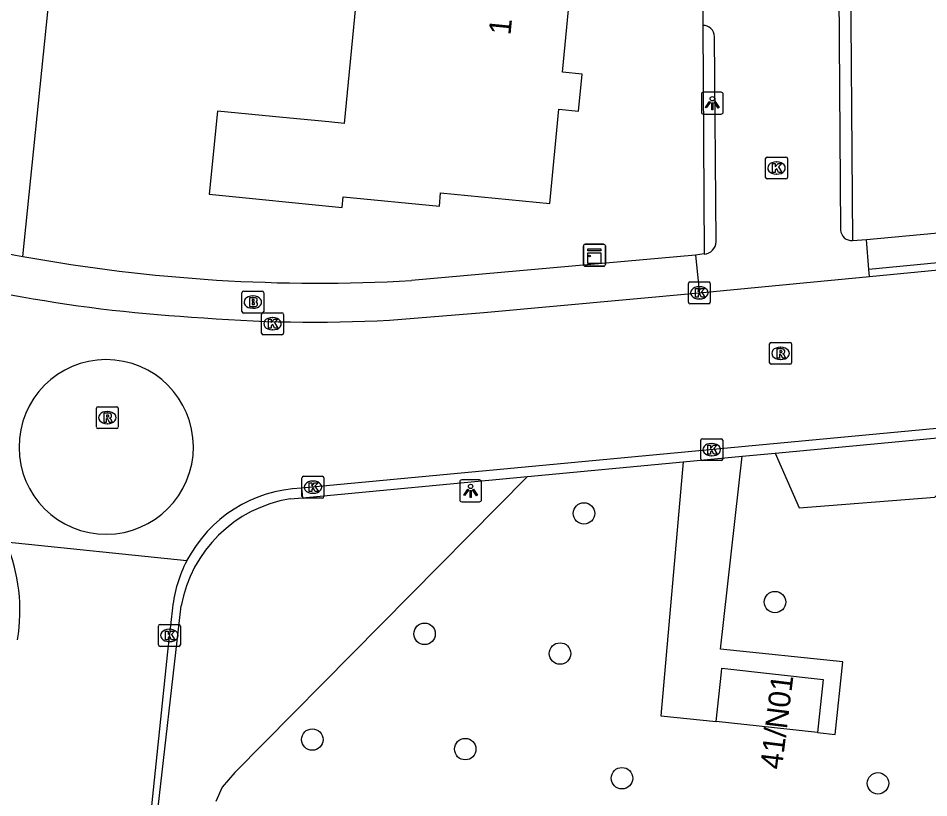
# Model space of a CAD drawing. Extents: x 162157 to 163165, y 378998 to 380775.
# Drawn here: x 162295.27 to 162336.77, y 380611.42 to 380646.95 of the extents above; entities that cross this region are included whole.
import ezdxf

# ---------------------------------------------------------------- set-up
doc = ezdxf.new("R2010")
doc.units = 0
for name, color, linetype in [('IMGEO_Boom', 7, 'Continuous'), ('IMGEO_Brandkraan', 7, 'Continuous'), ('IMGEO_Groenvoorziening', 7, 'Continuous'), ('IMGEO_Kast', 7, 'Continuous'), ('IMGEO_Kolk', 7, 'Continuous'), ('IMGEO_Lichtpunt', 7, 'Continuous'), ('IMGEO_Pand', 7, 'Continuous'), ('IMGEO_Pand_nummerreeks', 7, 'Continuous'), ('IMGEO_Rijbaan_lokaal_gesloten', 7, 'Continuous'), ('IMGEO_Rijbaan_lokaal_open', 7, 'Continuous'), ('IMGEO_Rioolput', 7, 'Continuous'), ('IMGEO_Voetpad_open', 7, 'Continuous')]:
    doc.layers.add(name, color=color, linetype=linetype)

msp = doc.modelspace()

# ---------------------------------------------------------------- linework, layer by layer
at = {"layer": 'IMGEO_Boom'}
for centre in [(162321.052, 380624.382), (162329.757, 380620.341), (162313.788, 380618.894), (162319.962, 380617.996), (162308.671, 380614.076), (162315.641, 380613.64), (162322.783, 380612.315), (162334.452, 380612.082)]:
    msp.add_circle(centre, 0.489, dxfattribs=at)
at = {"layer": 'IMGEO_Brandkraan'}
for p, q in [((162305.46, 380633.589), (162305.46, 380634.441)), ((162305.535, 380634.515), (162306.387, 380634.515)), ((162305.948, 380634.295), (162305.973, 380634.295)), ((162306.461, 380634.441), (162306.461, 380633.589)), ((162306.387, 380633.515), (162305.535, 380633.515)), ((162305.971, 380633.735), (162305.946, 380633.735))]:
    msp.add_line(p, q, dxfattribs=at)
for points in [[(162305.46, 380633.589), (162305.46, 380634.441)], [(162305.535, 380634.515), (162306.387, 380634.515)], [(162305.808, 380634.215), (162305.808, 380633.815), (162306.021, 380633.815)], [(162306.039, 380634.215), (162305.808, 380634.215)], [(162306.461, 380634.441), (162306.461, 380633.589)], [(162305.987, 380634.134), (162305.933, 380634.134), (162305.933, 380634.058)], [(162305.933, 380634.058), (162305.986, 380634.058)], [(162305.995, 380633.982), (162305.933, 380633.982), (162305.933, 380633.901)], [(162305.933, 380633.901), (162305.995, 380633.901)], [(162306.387, 380633.515), (162305.535, 380633.515)]]:
    msp.add_lwpolyline(points, dxfattribs=at)
for centre, radius, start, end in [((162305.537, 380634.439), 0.0765, 91.552, 178.448), ((162305.537, 380634.439), 0.0765, 91.552, 178.448), ((162306.043, 380634.07), 0.145, 59.4692, 91.5367), ((162306.385, 380634.439), 0.0765, 1.552, 88.448), ((162306.385, 380634.439), 0.0765, 1.552, 88.448), ((162305.988, 380634.096), 0.0379, 267.8285, 90.9355), ((162305.996, 380633.941), 0.0404, 269.8759, 90.5077), ((162306.027, 380634.066), 0.251, 268.6676, 293.5347), ((162306.068, 380634.117), 0.0922, 285.5137, 58.1501), ((162306.073, 380633.925), 0.105, 301.3115, 78.989), ((162305.537, 380633.591), 0.0765, 181.552, 268.448), ((162305.537, 380633.591), 0.0765, 181.552, 268.448), ((162306.385, 380633.591), 0.0765, 271.552, 358.448), ((162306.385, 380633.591), 0.0765, 271.552, 358.448)]:
    msp.add_arc(centre, radius, start, end, dxfattribs=at)
for centre, major_axis, ratio, start_param, end_param in [((162305.947, 380634.015), (-0.387, 0.002), 0.722429, 4.712389, 7.853982), ((162305.972, 380634.015), (-0.39, 0.002), 0.717154, 1.570796, 4.712389)]:
    msp.add_ellipse(centre, major_axis=major_axis, ratio=ratio, start_param=start_param, end_param=end_param, dxfattribs=at)
at = {"layer": 'IMGEO_Groenvoorziening'}
for points in [[(162295.473, 380636.096), (162301.962, 380699.607), (162302.171, 380699.713), (162304.371, 380721.939), (162315.245, 380730.525)], [(162329.764, 380627.128), (162330.857, 380624.636), (162337.051, 380625.119), (162337.938, 380625.997), (162339.039, 380626.343)], [(162318.483, 380626.064), (162305.138, 380612.567), (162304.556, 380611.905), (162304.277, 380611.251)]]:
    msp.add_lwpolyline(points, dxfattribs=at)
at = {"layer": 'IMGEO_Kast'}
for p, q in [((162321.028, 380635.725), (162321.028, 380636.566)), ((162321.028, 380636.566), (162321.028, 380635.725)), ((162321.103, 380636.65), (162321.944, 380636.65)), ((162321.944, 380636.65), (162321.103, 380636.65)), ((162322.028, 380636.575), (162322.028, 380635.734)), ((162322.028, 380635.734), (162322.028, 380636.575)), ((162321.953, 380635.65), (162321.112, 380635.65)), ((162321.112, 380635.65), (162321.953, 380635.65))]:
    msp.add_line(p, q, dxfattribs=at)
for points in [[(162321.223, 380636.44), (162321.823, 380636.44), (162321.823, 380636.355), (162321.223, 380636.355), (162321.223, 380636.44)], [(162321.223, 380636.265), (162321.823, 380636.265), (162321.823, 380635.776), (162321.223, 380635.776), (162321.223, 380636.265)]]:
    msp.add_lwpolyline(points, dxfattribs=at)
msp.add_circle((162321.307, 380636.114), 0.0377, dxfattribs=at)
for centre, start, end in [((162321.106, 380636.572), 92.4484, 184.2845), ((162321.106, 380636.572), 92.4484, 184.2845), ((162321.95, 380636.572), 2.4484, 94.2845), ((162321.95, 380636.572), 2.4484, 94.2845), ((162321.106, 380635.728), 182.4484, 274.2845), ((162321.106, 380635.728), 182.4484, 274.2845), ((162321.95, 380635.728), 272.4484, 4.2845), ((162321.95, 380635.728), 272.4484, 4.2845)]:
    msp.add_arc(centre, 0.0779, start, end, dxfattribs=at)
at = {"layer": 'IMGEO_Kolk'}
for p, q in [((162329.327, 380639.699), (162329.327, 380640.551)), ((162329.402, 380640.625), (162330.254, 380640.625)), ((162330.328, 380640.551), (162330.328, 380639.699)), ((162329.815, 380640.405), (162329.84, 380640.405)), ((162330.254, 380639.625), (162329.402, 380639.625)), ((162329.838, 380639.845), (162329.813, 380639.845)), ((162325.81, 380634.01), (162325.81, 380634.862)), ((162325.885, 380634.936), (162326.737, 380634.936)), ((162326.298, 380634.716), (162326.323, 380634.716)), ((162326.811, 380634.862), (162326.811, 380634.01)), ((162326.737, 380633.936), (162325.885, 380633.936)), ((162326.321, 380634.156), (162326.296, 380634.156)), ((162306.357, 380632.603), (162306.357, 380633.455)), ((162306.432, 380633.529), (162307.284, 380633.529)), ((162307.358, 380633.455), (162307.358, 380632.603)), ((162306.845, 380633.309), (162306.87, 380633.309)), ((162306.868, 380632.749), (162306.843, 380632.749)), ((162307.284, 380632.529), (162306.432, 380632.529)), ((162326.377, 380626.862), (162326.377, 380627.714)), ((162326.452, 380627.788), (162327.304, 380627.788)), ((162326.865, 380627.568), (162326.89, 380627.568)), ((162327.378, 380627.714), (162327.378, 380626.862)), ((162327.304, 380626.788), (162326.452, 380626.788)), ((162326.888, 380627.008), (162326.863, 380627.008)), ((162308.201, 380625.152), (162308.201, 380626.004)), ((162308.276, 380626.078), (162309.128, 380626.078)), ((162309.202, 380626.004), (162309.202, 380625.152)), ((162308.689, 380625.858), (162308.714, 380625.858)), ((162309.128, 380625.078), (162308.276, 380625.078)), ((162308.712, 380625.298), (162308.687, 380625.298)), ((162301.732, 380619.322), (162302.584, 380619.322)), ((162301.657, 380618.396), (162301.657, 380619.248)), ((162302.145, 380619.102), (162302.17, 380619.102)), ((162302.658, 380619.248), (162302.658, 380618.396)), ((162302.168, 380618.542), (162302.143, 380618.542)), ((162302.584, 380618.322), (162301.732, 380618.322))]:
    msp.add_line(p, q, dxfattribs=at)
for points in [[(162329.327, 380639.699), (162329.327, 380640.551)], [(162329.402, 380640.625), (162330.254, 380640.625)], [(162330.328, 380640.551), (162330.328, 380639.699)], [(162329.648, 380640.325), (162329.771, 380640.325), (162329.771, 380640.174), (162329.901, 380640.325), (162330.065, 380640.325), (162329.919, 380640.174), (162330.072, 380639.925), (162329.92, 380639.925), (162329.835, 380640.089), (162329.771, 380640.022), (162329.771, 380639.925), (162329.648, 380639.925), (162329.648, 380640.325)], [(162330.254, 380639.625), (162329.402, 380639.625)], [(162325.81, 380634.01), (162325.81, 380634.862)], [(162325.885, 380634.936), (162326.737, 380634.936)], [(162326.131, 380634.636), (162326.254, 380634.636), (162326.254, 380634.485), (162326.384, 380634.636), (162326.548, 380634.636), (162326.402, 380634.485), (162326.555, 380634.236), (162326.403, 380634.236), (162326.318, 380634.4), (162326.254, 380634.333), (162326.254, 380634.236), (162326.131, 380634.236), (162326.131, 380634.636)], [(162326.811, 380634.862), (162326.811, 380634.01)], [(162326.737, 380633.936), (162325.885, 380633.936)], [(162306.357, 380632.603), (162306.357, 380633.455)], [(162306.432, 380633.529), (162307.284, 380633.529)], [(162307.358, 380633.455), (162307.358, 380632.603)], [(162306.678, 380633.229), (162306.801, 380633.229), (162306.801, 380633.078), (162306.931, 380633.229), (162307.095, 380633.229), (162306.949, 380633.078), (162307.102, 380632.829), (162306.95, 380632.829), (162306.865, 380632.993), (162306.801, 380632.926), (162306.801, 380632.829), (162306.678, 380632.829), (162306.678, 380633.229)], [(162307.284, 380632.529), (162306.432, 380632.529)], [(162326.377, 380626.862), (162326.377, 380627.714)], [(162326.452, 380627.788), (162327.304, 380627.788)], [(162327.378, 380627.714), (162327.378, 380626.862)], [(162326.698, 380627.488), (162326.821, 380627.488), (162326.821, 380627.337), (162326.951, 380627.488), (162327.115, 380627.488), (162326.969, 380627.337), (162327.122, 380627.088), (162326.97, 380627.088), (162326.885, 380627.252), (162326.821, 380627.185), (162326.821, 380627.088), (162326.698, 380627.088), (162326.698, 380627.488)], [(162327.304, 380626.788), (162326.452, 380626.788)], [(162308.201, 380625.152), (162308.201, 380626.004)], [(162308.276, 380626.078), (162309.128, 380626.078)], [(162309.202, 380626.004), (162309.202, 380625.152)], [(162308.522, 380625.778), (162308.645, 380625.778), (162308.645, 380625.627), (162308.775, 380625.778), (162308.939, 380625.778), (162308.793, 380625.627), (162308.946, 380625.378), (162308.794, 380625.378), (162308.709, 380625.542), (162308.645, 380625.475), (162308.645, 380625.378), (162308.522, 380625.378), (162308.522, 380625.778)], [(162309.128, 380625.078), (162308.276, 380625.078)], [(162301.732, 380619.322), (162302.584, 380619.322)], [(162301.657, 380618.396), (162301.657, 380619.248)], [(162301.978, 380619.022), (162302.101, 380619.022), (162302.101, 380618.871), (162302.231, 380619.022), (162302.395, 380619.022), (162302.249, 380618.871), (162302.402, 380618.622), (162302.25, 380618.622), (162302.165, 380618.786), (162302.101, 380618.719), (162302.101, 380618.622), (162301.978, 380618.622), (162301.978, 380619.022)], [(162302.658, 380619.248), (162302.658, 380618.396)], [(162302.584, 380618.322), (162301.732, 380618.322)]]:
    msp.add_lwpolyline(points, dxfattribs=at)
for centre, start, end in [((162329.404, 380640.549), 91.552, 178.448), ((162329.404, 380640.549), 91.552, 178.448), ((162330.252, 380640.549), 1.552, 88.448), ((162330.252, 380640.549), 1.552, 88.448), ((162329.404, 380639.701), 181.552, 268.448), ((162329.404, 380639.701), 181.552, 268.448), ((162330.252, 380639.701), 271.552, 358.448), ((162330.252, 380639.701), 271.552, 358.448), ((162325.887, 380634.86), 91.552, 178.448), ((162325.887, 380634.86), 91.552, 178.448), ((162326.735, 380634.86), 1.552, 88.448), ((162326.735, 380634.86), 1.552, 88.448), ((162325.887, 380634.012), 181.552, 268.448), ((162325.887, 380634.012), 181.552, 268.448), ((162326.735, 380634.012), 271.552, 358.448), ((162326.735, 380634.012), 271.552, 358.448), ((162306.434, 380633.453), 91.552, 178.448), ((162306.434, 380633.453), 91.552, 178.448), ((162307.282, 380633.453), 1.552, 88.448), ((162307.282, 380633.453), 1.552, 88.448), ((162306.434, 380632.605), 181.552, 268.448), ((162306.434, 380632.605), 181.552, 268.448), ((162307.282, 380632.605), 271.552, 358.448), ((162307.282, 380632.605), 271.552, 358.448), ((162326.454, 380627.712), 91.552, 178.448), ((162326.454, 380627.712), 91.552, 178.448), ((162327.302, 380627.712), 1.552, 88.448), ((162327.302, 380627.712), 1.552, 88.448), ((162326.454, 380626.864), 181.552, 268.448), ((162326.454, 380626.864), 181.552, 268.448), ((162327.302, 380626.864), 271.552, 358.448), ((162327.302, 380626.864), 271.552, 358.448), ((162308.278, 380626.002), 91.552, 178.448), ((162308.278, 380626.002), 91.552, 178.448), ((162309.126, 380626.002), 1.552, 88.448), ((162309.126, 380626.002), 1.552, 88.448), ((162308.278, 380625.154), 181.552, 268.448), ((162308.278, 380625.154), 181.552, 268.448), ((162309.126, 380625.154), 271.552, 358.448), ((162309.126, 380625.154), 271.552, 358.448), ((162301.734, 380619.246), 91.552, 178.448), ((162301.734, 380619.246), 91.552, 178.448), ((162302.582, 380619.246), 1.552, 88.448), ((162302.582, 380619.246), 1.552, 88.448), ((162301.734, 380618.398), 181.552, 268.448), ((162301.734, 380618.398), 181.552, 268.448), ((162302.582, 380618.398), 271.552, 358.448), ((162302.582, 380618.398), 271.552, 358.448)]:
    msp.add_arc(centre, 0.0765, start, end, dxfattribs=at)
for centre, major_axis, ratio, start_param, end_param in [((162329.814, 380640.125), (-0.387, 0.002), 0.722429, 4.712389, 7.853982), ((162329.839, 380640.125), (-0.39, 0.002), 0.717154, 1.570796, 4.712389), ((162326.297, 380634.436), (-0.387, 0.002), 0.722429, 4.712389, 7.853982), ((162326.322, 380634.436), (-0.39, 0.002), 0.717154, 1.570796, 4.712389), ((162306.844, 380633.029), (-0.387, 0.002), 0.722429, 4.712389, 7.853982), ((162306.869, 380633.029), (-0.39, 0.002), 0.717154, 1.570796, 4.712389), ((162326.864, 380627.288), (-0.387, 0.002), 0.722429, 4.712389, 7.853982), ((162326.889, 380627.288), (-0.39, 0.002), 0.717154, 1.570796, 4.712389), ((162308.688, 380625.578), (-0.387, 0.002), 0.722429, 4.712389, 7.853982), ((162308.713, 380625.578), (-0.39, 0.002), 0.717154, 1.570796, 4.712389), ((162302.144, 380618.822), (-0.387, 0.002), 0.722429, 4.712389, 7.853982), ((162302.169, 380618.822), (-0.39, 0.002), 0.717154, 1.570796, 4.712389)]:
    msp.add_ellipse(centre, major_axis=major_axis, ratio=ratio, start_param=start_param, end_param=end_param, dxfattribs=at)
at = {"layer": 'IMGEO_Lichtpunt'}
for p, q in [((162326.404, 380643.486), (162326.404, 380642.679)), ((162326.404, 380643.486), (162326.404, 380642.679)), ((162327.306, 380643.581), (162326.498, 380643.581)), ((162327.306, 380643.581), (162326.498, 380643.581)), ((162327.4, 380642.679), (162327.4, 380643.486)), ((162327.4, 380642.679), (162327.4, 380643.486)), ((162326.498, 380642.585), (162327.306, 380642.585)), ((162326.498, 380642.585), (162327.306, 380642.585)), ((162316.29, 380625.913), (162315.482, 380625.913)), ((162316.29, 380625.913), (162315.482, 380625.913)), ((162315.388, 380625.818), (162315.388, 380625.011)), ((162315.388, 380625.818), (162315.388, 380625.011)), ((162316.384, 380625.011), (162316.384, 380625.818)), ((162316.384, 380625.011), (162316.384, 380625.818)), ((162315.482, 380624.917), (162316.29, 380624.917)), ((162315.482, 380624.917), (162316.29, 380624.917))]:
    msp.add_line(p, q, dxfattribs=at)
for points in [[(162326.778, 380643.15), (162326.817, 380643.122), (162326.629, 380642.86), (162326.591, 380642.887), (162326.778, 380643.15)], [(162326.88, 380643.102), (162326.927, 380643.102), (162326.927, 380642.78), (162326.88, 380642.78), (162326.88, 380643.102)], [(162326.99, 380643.122), (162327.028, 380643.149), (162327.215, 380642.887), (162327.176, 380642.859), (162326.99, 380643.122)], [(162315.762, 380625.482), (162315.801, 380625.454), (162315.613, 380625.192), (162315.575, 380625.219), (162315.762, 380625.482)], [(162315.974, 380625.454), (162316.012, 380625.481), (162316.199, 380625.219), (162316.16, 380625.191), (162315.974, 380625.454)], [(162315.864, 380625.434), (162315.911, 380625.434), (162315.911, 380625.112), (162315.864, 380625.112), (162315.864, 380625.434)]]:
    msp.add_lwpolyline(points, dxfattribs=at)
for centre in [(162326.903, 380643.284), (162315.887, 380625.616)]:
    msp.add_circle(centre, 0.0994, dxfattribs=at)
for centre, start, end in [((162326.498, 380643.486), 90, 180), ((162326.498, 380643.486), 90, 180), ((162327.306, 380643.486), 0, 90), ((162327.306, 380643.486), 0, 90), ((162326.498, 380642.679), 180, 270), ((162326.498, 380642.679), 180, 270), ((162327.306, 380642.679), 270, 0), ((162327.306, 380642.679), 270, 360), ((162315.482, 380625.818), 90, 180), ((162315.482, 380625.818), 90, 180), ((162316.29, 380625.818), 0, 90), ((162316.29, 380625.818), 0, 90), ((162315.482, 380625.011), 180, 270), ((162315.482, 380625.011), 180, 270), ((162316.29, 380625.011), 270, 0), ((162316.29, 380625.011), 270, 360)]:
    msp.add_arc(centre, 0.0946, start, end, dxfattribs=at)
at = {"layer": 'IMGEO_Pand'}
for points in [[(162309.421, 380642.222), (162307.322, 380642.425), (162304.345, 380642.714), (162303.969, 380638.932), (162310.032, 380638.321), (162310.084, 380638.818), (162314.475, 380638.387), (162314.518, 380638.991), (162319.498, 380638.507), (162319.905, 380642.803), (162320.8, 380642.716), (162320.964, 380644.404), (162320.068, 380644.491), (162320.926, 380653.349)], [(162310.634, 380647.479), (162310.118, 380642.154), (162309.421, 380642.222)], [(162327.07, 380614.906), (162327.317, 380617.154), (162327.336, 380617.327), (162331.955, 380616.819), (162331.689, 380614.398)], [(162331.689, 380614.398), (162327.07, 380614.906)]]:
    msp.add_lwpolyline(points, dxfattribs=at)
at = {"layer": 'IMGEO_Rijbaan_lokaal_gesloten'}
for points in [[(162334.069, 380635.183), (162337.675, 380635.531), (162411.727, 380642.392), (162421.757, 380643.305)], [(162437.427, 380637.652), (162415.859, 380635.682), (162364.95, 380630.872), (162308.18, 380625.53)], [(162326.307, 380634.434), (162334.069, 380635.183)], [(162312.194, 380633.191), (162316.483, 380633.533), (162326.307, 380634.434)], [(162329.764, 380627.128), (162364.046, 380630.361)], [(162318.483, 380626.064), (162325.57, 380626.732)], [(162325.57, 380626.732), (162328.269, 380626.987)], [(162328.269, 380626.987), (162329.764, 380627.128)], [(162308.221, 380625.096), (162318.483, 380626.064)], [(162308.18, 380625.53), (162308.221, 380625.096)], [(162302.945, 380622.215), (162294.71, 380623.071)], [(162302.301, 380620.086), (162302.073, 380618.08), (162298.145, 380580.349), (162293.721, 380538.975), (162292.56, 380528.03)]]:
    msp.add_lwpolyline(points, dxfattribs=at)
for centre, radius, start, end in [((162307.22, 380700.224), 67.013, 252.34085, 266.53125), ((162308.722, 380699.115), 66.015, 265.17086, 273.01441), ((162308.389, 380619.408), 6.125, 91.9596, 152.7275), ((162287.419, 380619.961), 7.926, 350.24, 23.1035), ((162308.358, 380619.416), 6.094, 152.6544, 173.6856)]:
    msp.add_arc(centre, radius, start, end, dxfattribs=at)
at = {"layer": 'IMGEO_Rijbaan_lokaal_open'}
for points in [[(162326.48, 380655.187), (162326.471, 380646.623)], [(162332.659, 380650.286), (162332.751, 380637.296)], [(162327.074, 380636.761), (162327.007, 380646.112)], [(162358.96, 380637.825), (162337.644, 380635.85), (162334.038, 380635.502)], [(162333.284, 380636.819), (162333.922, 380636.869)], [(162334.038, 380635.502), (162333.922, 380636.869)], [(162326.53, 380636.206), (162326.139, 380636.156)], [(162326.139, 380636.156), (162326.268, 380634.832), (162326.307, 380634.434)], [(162334.069, 380635.183), (162334.038, 380635.502)], [(162307.66, 380625.043), (162308.221, 380625.096)], [(162299.562, 380590.653), (162301.518, 380609.937), (162302.695, 380620.164)]]:
    msp.add_lwpolyline(points, dxfattribs=at)
for centre, radius, start, end in [((162326.474, 380646.09), 0.533, 2.3672, 90.3684), ((162333.25, 380637.317), 0.499, 182.4332, 273.9139), ((162326.508, 380636.771), 0.566, 272.2057, 358.9412), ((162299.285, 380627.411), 3.981, 84.5124, 264.4616), ((162299.272, 380627.412), 3.981, 264.6536, 84.3204), ((162308.615, 380619.105), 6.014, 99.1377, 169.8613)]:
    msp.add_arc(centre, radius, start, end, dxfattribs=at)
at = {"layer": 'IMGEO_Rioolput'}
for p, q in [((162329.586, 380632.178), (162330.438, 380632.178)), ((162329.511, 380631.252), (162329.511, 380632.104)), ((162329.999, 380631.958), (162330.024, 380631.958)), ((162330.512, 380632.104), (162330.512, 380631.252)), ((162330.022, 380631.398), (162329.997, 380631.398)), ((162330.438, 380631.178), (162329.586, 380631.178)), ((162298.904, 380629.247), (162299.756, 380629.247)), ((162298.829, 380628.321), (162298.829, 380629.173)), ((162299.317, 380629.027), (162299.342, 380629.027)), ((162299.83, 380629.173), (162299.83, 380628.321)), ((162299.34, 380628.467), (162299.315, 380628.467)), ((162299.756, 380628.247), (162298.904, 380628.247))]:
    msp.add_line(p, q, dxfattribs=at)
for points in [[(162329.586, 380632.178), (162330.438, 380632.178)], [(162329.511, 380631.252), (162329.511, 380632.104)], [(162330.1, 380631.876), (162329.848, 380631.878), (162329.848, 380631.478)], [(162330.026, 380631.797), (162329.972, 380631.797), (162329.972, 380631.716)], [(162329.972, 380631.716), (162330.024, 380631.716)], [(162330.512, 380632.104), (162330.512, 380631.252)], [(162329.848, 380631.478), (162329.972, 380631.478), (162329.972, 380631.64), (162329.983, 380631.64)], [(162330.03, 380631.611), (162330.101, 380631.478), (162330.241, 380631.478), (162330.176, 380631.604)], [(162330.438, 380631.178), (162329.586, 380631.178)], [(162298.904, 380629.247), (162299.756, 380629.247)], [(162298.829, 380628.321), (162298.829, 380629.173)], [(162299.418, 380628.945), (162299.166, 380628.947), (162299.166, 380628.547)], [(162299.344, 380628.866), (162299.29, 380628.866), (162299.29, 380628.785)], [(162299.83, 380629.173), (162299.83, 380628.321)], [(162299.166, 380628.547), (162299.29, 380628.547), (162299.29, 380628.709), (162299.301, 380628.709)], [(162299.29, 380628.785), (162299.342, 380628.785)], [(162299.348, 380628.68), (162299.419, 380628.547), (162299.559, 380628.547), (162299.494, 380628.673)], [(162299.756, 380628.247), (162298.904, 380628.247)]]:
    msp.add_lwpolyline(points, dxfattribs=at)
for centre, radius, start, end in [((162329.588, 380632.102), 0.0765, 91.552, 178.448), ((162329.588, 380632.102), 0.0765, 91.552, 178.448), ((162330.436, 380632.102), 0.0765, 1.552, 88.448), ((162330.436, 380632.102), 0.0765, 1.552, 88.448), ((162330.008, 380631.905), 0.19, 274.7715, 282.9687), ((162330.032, 380631.701), 0.0964, 77.0061, 93.1865), ((162330.046, 380631.758), 0.0378, 276.6634, 79.6772), ((162330.099, 380631.766), 0.109, 350.3612, 89.416), ((162330.097, 380631.766), 0.112, 277.5842, 350.9817), ((162329.982, 380631.587), 0.0533, 26.0293, 88.6989), ((162330.081, 380631.551), 0.108, 29.5134, 73.7905), ((162329.588, 380631.254), 0.0765, 181.552, 268.448), ((162329.588, 380631.254), 0.0765, 181.552, 268.448), ((162330.436, 380631.254), 0.0765, 271.552, 358.448), ((162330.436, 380631.254), 0.0765, 271.552, 358.448), ((162298.906, 380629.171), 0.0765, 91.552, 178.448), ((162298.906, 380629.171), 0.0765, 91.552, 178.448), ((162299.754, 380629.171), 0.0765, 1.552, 88.448), ((162299.754, 380629.171), 0.0765, 1.552, 88.448), ((162299.35, 380628.77), 0.0964, 77.0061, 93.1865), ((162299.364, 380628.827), 0.0378, 276.6634, 79.6772), ((162299.417, 380628.835), 0.109, 350.3612, 89.416), ((162299.415, 380628.835), 0.112, 277.5842, 350.9817), ((162299.3, 380628.656), 0.0533, 26.0293, 88.6989), ((162299.326, 380628.974), 0.19, 274.7715, 282.9687), ((162299.399, 380628.62), 0.108, 29.5134, 73.7905), ((162298.906, 380628.323), 0.0765, 181.552, 268.448), ((162298.906, 380628.323), 0.0765, 181.552, 268.448), ((162299.754, 380628.323), 0.0765, 271.552, 358.448), ((162299.754, 380628.323), 0.0765, 271.552, 358.448)]:
    msp.add_arc(centre, radius, start, end, dxfattribs=at)
for centre, major_axis, ratio, start_param, end_param in [((162329.998, 380631.678), (-0.387, 0.002), 0.722429, 4.712389, 7.853982), ((162330.023, 380631.678), (-0.39, 0.002), 0.717154, 1.570796, 4.712389), ((162299.316, 380628.747), (-0.387, 0.002), 0.722429, 4.712389, 7.853982), ((162299.341, 380628.747), (-0.39, 0.002), 0.717154, 1.570796, 4.712389)]:
    msp.add_ellipse(centre, major_axis=major_axis, ratio=ratio, start_param=start_param, end_param=end_param, dxfattribs=at)
at = {"layer": 'IMGEO_Voetpad_open'}
for points in [[(162333.191, 380650.844), (162333.284, 380636.819)], [(162326.471, 380646.623), (162326.53, 380636.206)], [(162333.922, 380636.869), (162421.612, 380645.024)], [(162326.139, 380636.156), (162313.193, 380634.993)], [(162325.57, 380626.732), (162324.561, 380615.16), (162327.07, 380614.906)], [(162331.689, 380614.398), (162332.496, 380614.313), (162332.843, 380617.611), (162327.276, 380618.196), (162328.269, 380626.987)]]:
    msp.add_lwpolyline(points, dxfattribs=at)
for centre, radius, start, end in [((162308.715, 380708.75), 73.851, 257.62463, 259.67027), ((162308.978, 380710.164), 75.289, 259.66682, 273.2095)]:
    msp.add_arc(centre, radius, start, end, dxfattribs=at)

# ---------------------------------------------------------------- texts
at = {"layer": 'IMGEO_Pand_nummerreeks'}
for s, rotation, p in [('1', 84.5026, (162317.703, 380646.158)), ('41/N01', 82.9188, (162330.069, 380612.68))]:
    msp.add_text(s, height=1, rotation=rotation, dxfattribs=at).set_placement(p)

doc.saveas('drawing.dxf')
